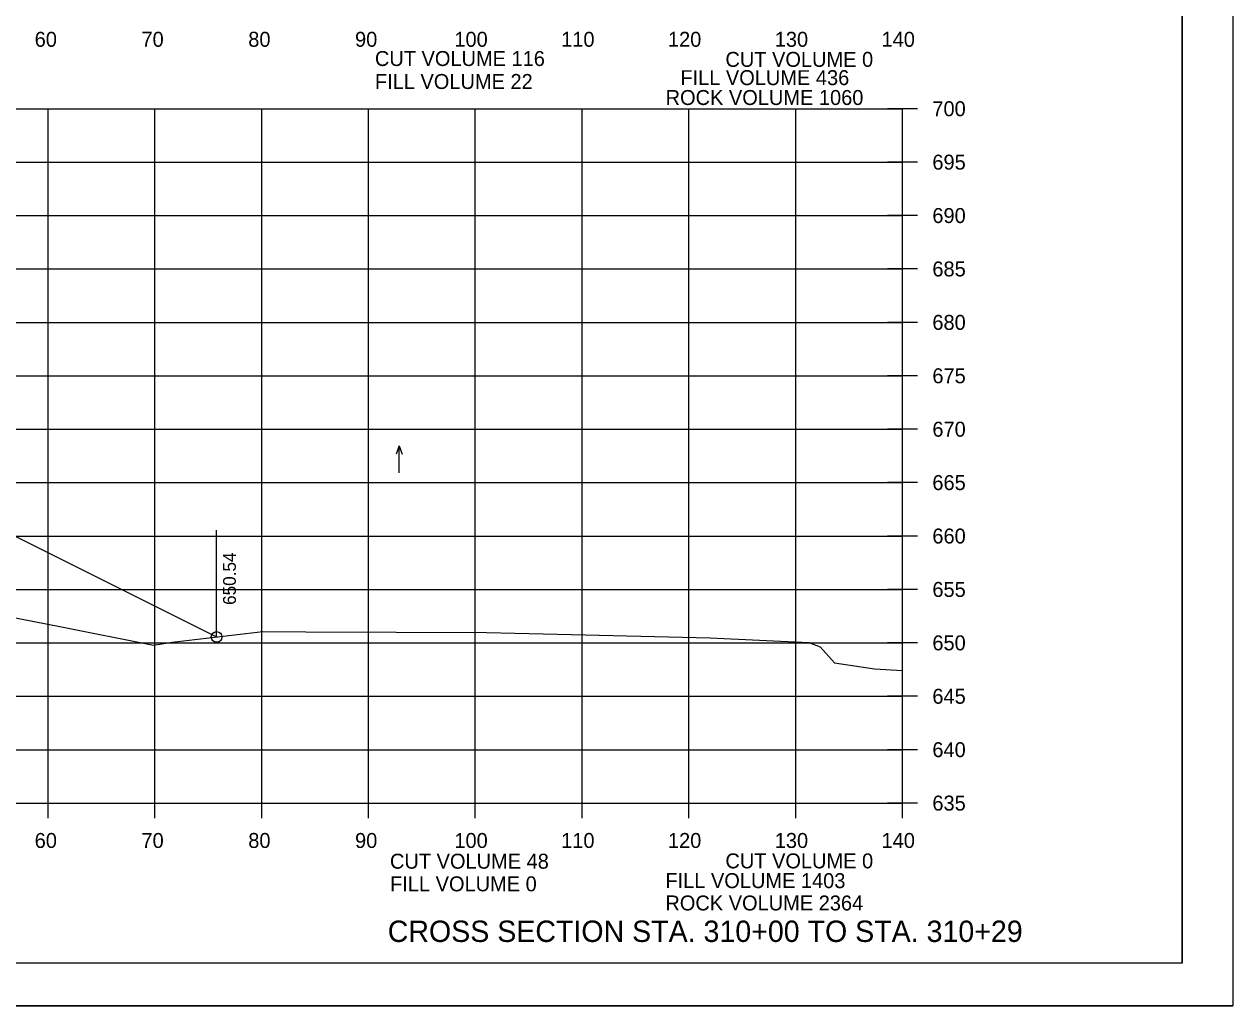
# Model space of a CAD drawing. Extents: x 1370515 to 1370849, y 383299 to 386073.
# Drawn here: x 1370735.6 to 1370848.7, y 384792.8 to 384884.7 of the extents above; entities that cross this region are included whole.
import ezdxf

# ---------------------------------------------------------------- set-up
doc = ezdxf.new("R2010")
doc.units = 0
for name, color, linetype in [('R_Axis', 7, 'Continuous'), ('R_Axis Annot', 7, 'Continuous'), ('R_Border', 7, 'Continuous'), ('R_Draft', 7, 'Continuous'), ('R_Exist Surface', 7, 'Continuous'), ('R_Fin Surface', 7, 'Continuous'), ('R_Grid', 7, 'Continuous'), ('R_No Plot', 7, 'Continuous'), ('R_Water Annot', 7, 'Continuous'), ('R_Xsect Elev', 7, 'Continuous')]:
    doc.layers.add(name, color=color, linetype=linetype)

msp = doc.modelspace()

# ---------------------------------------------------------------- linework, layer by layer
at = {"layer": 'R_Axis'}
for p, q in [((1370819.2, 384876.77), (1370816.4, 384876.77)), ((1370817.8, 384811.77), (1370817.8, 384876.77)), ((1370819.2, 384871.77), (1370816.4, 384871.77)), ((1370819.2, 384866.77), (1370816.4, 384866.77)), ((1370819.2, 384861.77), (1370816.4, 384861.77)), ((1370819.2, 384856.77), (1370816.4, 384856.77)), ((1370819.2, 384851.77), (1370816.4, 384851.77)), ((1370819.2, 384846.77), (1370816.4, 384846.77)), ((1370819.2, 384841.77), (1370816.4, 384841.77)), ((1370819.2, 384836.77), (1370816.4, 384836.77)), ((1370819.2, 384831.77), (1370816.4, 384831.77)), ((1370819.2, 384826.77), (1370816.4, 384826.77)), ((1370819.2, 384821.77), (1370816.4, 384821.77)), ((1370819.2, 384816.77), (1370816.4, 384816.77)), ((1370737.8, 384810.37), (1370737.8, 384813.17)), ((1370747.8, 384810.37), (1370747.8, 384813.17)), ((1370757.8, 384810.37), (1370757.8, 384813.17)), ((1370767.8, 384810.37), (1370767.8, 384813.17)), ((1370777.8, 384810.37), (1370777.8, 384813.17)), ((1370787.8, 384810.37), (1370787.8, 384813.17)), ((1370797.8, 384810.37), (1370797.8, 384813.17)), ((1370807.8, 384810.37), (1370807.8, 384813.17)), ((1370817.8, 384810.37), (1370817.8, 384813.17)), ((1370537.8, 384811.77), (1370817.8, 384811.77)), ((1370819.2, 384811.77), (1370816.4, 384811.77))]:
    msp.add_line(p, q, dxfattribs=at)
at = {"layer": 'R_Border'}
for q in [(1370843.98, 385002.23), (1370527.8, 384796.77)]:
    msp.add_line((1370843.98, 384796.77), q, dxfattribs=at)
at = {"layer": 'R_Exist Surface'}
msp.add_lwpolyline([(1370724.94, 384831.01), (1370738.9, 384828.29), (1370747.66, 384826.54), (1370749.43, 384826.82), (1370757.89, 384827.83), (1370761.92, 384827.81), (1370778.86, 384827.75), (1370786.81, 384827.55), (1370799.8, 384827.24), (1370809.02, 384826.81), (1370810.09, 384826.4), (1370811.42, 384824.9), (1370815.19, 384824.35), (1370817.8, 384824.18)], dxfattribs=at)
at = {"layer": 'R_Fin Surface'}
msp.add_lwpolyline([(1370606.07, 384852.53), (1370623.41, 384846.74), (1370627.3, 384848.02), (1370632.71, 384849.88), (1370651.8, 384856.21), (1370657.8, 384857.71), (1370665.8, 384856.91), (1370677.8, 384855.71), (1370689.8, 384854.51), (1370697.8, 384853.71), (1370703.8, 384852.21), (1370708.65, 384849.78), (1370753.58, 384827.32)], dxfattribs=at)
at = {"layer": 'R_Grid'}
for p, q in [((1370537.8, 384876.77), (1370817.8, 384876.77)), ((1370737.8, 384811.77), (1370737.8, 384876.77)), ((1370747.8, 384811.77), (1370747.8, 384876.77)), ((1370757.8, 384811.77), (1370757.8, 384876.77)), ((1370767.8, 384811.77), (1370767.8, 384876.77)), ((1370777.8, 384811.77), (1370777.8, 384876.77)), ((1370787.8, 384811.77), (1370787.8, 384876.77)), ((1370797.8, 384811.77), (1370797.8, 384876.77)), ((1370807.8, 384811.77), (1370807.8, 384876.77)), ((1370817.8, 384811.77), (1370817.8, 384876.77)), ((1370537.8, 384871.77), (1370817.8, 384871.77)), ((1370537.8, 384866.77), (1370817.8, 384866.77)), ((1370537.8, 384861.77), (1370817.8, 384861.77)), ((1370537.8, 384856.77), (1370817.8, 384856.77)), ((1370537.8, 384851.77), (1370817.8, 384851.77)), ((1370537.8, 384846.77), (1370817.8, 384846.77)), ((1370537.8, 384841.77), (1370817.8, 384841.77)), ((1370537.8, 384836.77), (1370817.8, 384836.77)), ((1370537.8, 384831.77), (1370817.8, 384831.77)), ((1370537.8, 384826.77), (1370817.8, 384826.77)), ((1370537.8, 384821.77), (1370817.8, 384821.77)), ((1370537.8, 384816.77), (1370817.8, 384816.77)), ((1370537.8, 384811.77), (1370817.8, 384811.77))]:
    msp.add_line(p, q, dxfattribs=at)
at = {"layer": 'R_No Plot'}
msp.add_line((1370515.4, 384792.8), (1370848.73, 384792.8), dxfattribs=at)
for points in [[(1370515.39, 385006.13), (1370848.73, 385006.13), (1370848.73, 384792.79), (1370515.39, 384792.79)], [(1370761.72, 385002.23), (1370761.72, 384992.35), (1370797.45, 384992.35), (1370797.45, 384989.43), (1370820.65, 384989.43), (1370820.65, 384966.22), (1370843.98, 384966.22), (1370843.98, 384796.77), (1370527.8, 384796.77), (1370527.8, 385002.23)]]:
    msp.add_lwpolyline(points, close=True, dxfattribs=at)
msp.add_circle((1370753.58, 384827.32), 0.5, dxfattribs=at)
at = {"layer": 'R_Water Annot'}
for p, q in [((1370770.68, 384845.21), (1370770.4, 384844.44)), ((1370770.68, 384842.69), (1370770.68, 384845.21)), ((1370770.68, 384845.21), (1370770.96, 384844.44))]:
    msp.add_line(p, q, dxfattribs=at)
at = {"layer": 'R_Xsect Elev'}
msp.add_line((1370753.58, 384827.32), (1370753.58, 384837.32), dxfattribs=at)

# ---------------------------------------------------------------- texts
at = {"layer": 'R_Axis Annot'}
for s, p in [('60', (1370736.54, 384882.57)), ('70', (1370746.54, 384882.57)), ('80', (1370756.54, 384882.57)), ('90', (1370766.54, 384882.57)), ('100', (1370775.84, 384882.57)), ('110', (1370785.84, 384882.57)), ('120', (1370795.84, 384882.57)), ('130', (1370805.84, 384882.57)), ('140', (1370815.84, 384882.57)), ('CUT VOLUME 116', (1370768.4, 384880.77)), ('CUT VOLUME 0', (1370801.22, 384880.69)), ('FILL VOLUME 22', (1370768.4, 384878.62)), ('FILL VOLUME 436', (1370797, 384878.98)), ('ROCK VOLUME 1060', (1370795.62, 384877.12)), ('700', (1370820.6, 384876.07)), ('695', (1370820.6, 384871.07)), ('690', (1370820.6, 384866.07)), ('685', (1370820.6, 384861.07)), ('680', (1370820.6, 384856.07)), ('675', (1370820.6, 384851.07)), ('670', (1370820.6, 384846.07)), ('665', (1370820.6, 384841.07)), ('660', (1370820.6, 384836.07)), ('655', (1370820.6, 384831.07)), ('650', (1370820.6, 384826.07)), ('645', (1370820.6, 384821.07)), ('640', (1370820.6, 384816.07)), ('635', (1370820.6, 384811.07)), ('60', (1370736.54, 384807.57)), ('70', (1370746.54, 384807.57)), ('80', (1370756.54, 384807.57)), ('90', (1370766.54, 384807.57)), ('100', (1370775.84, 384807.57)), ('110', (1370785.84, 384807.57)), ('120', (1370795.84, 384807.57)), ('130', (1370805.84, 384807.57)), ('140', (1370815.84, 384807.57)), ('CUT VOLUME 48', (1370769.81, 384805.63)), ('CUT VOLUME 0', (1370801.22, 384805.66)), ('FILL VOLUME 0', (1370769.82, 384803.51)), ('FILL VOLUME 1403', (1370795.6, 384803.81)), ('ROCK VOLUME 2364', (1370795.6, 384801.72))]:
    msp.add_text(s, height=1.4, dxfattribs=at).set_placement(p)
at = {"layer": 'R_Draft'}
msp.add_text('CROSS SECTION STA. 310+00 TO STA. 310+29', height=2, dxfattribs=at).set_placement((1370769.6, 384798.77))
at = {"layer": 'R_No Plot'}
for p in [(1370757.85, 384827.78), (1370778.81, 384827.7), (1370747.61, 384826.49), (1370808.97, 384826.76), (1370811.38, 384824.85)]:
    msp.add_text('+', height=0.1, dxfattribs=at).set_placement(p)
at = {"layer": 'R_Xsect Elev'}
msp.add_text('650.54', height=1.2, rotation=90, dxfattribs=at).set_placement((1370755.38, 384830.32))

doc.saveas('drawing.dxf')
